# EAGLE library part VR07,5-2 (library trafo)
TRANSFORMER 1 primary winding, 2 secondary windings, mounting holes BLOCK
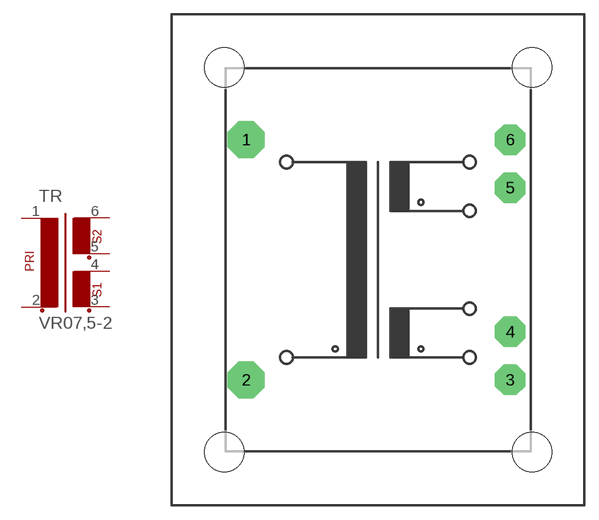
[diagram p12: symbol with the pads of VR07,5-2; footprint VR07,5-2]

Designator prefix TR

## VR07,5-2  [VR07,5-2]
1  1  pas
2  2  pas
3  3  pas
4  4  pas
5  5  pas
6  6  pas

## Footprint VR07,5-2 (pad centres in mm)
TRANSFORMER 1 primary winding, 2 secondary windings, mounting holes
drill 1.397 pad 3.81 octagon: 1 -13.741,12.497; 2 -13.741,-12.497
drill 1.397 pad 3.175 octagon: 3 13.741,-12.497; 4 13.741,-7.493; 5 13.741,7.493; 6 13.741,12.497
hole 4.115 at -16.002,-19.99
hole 4.115 at 16.002,-19.99
hole 4.115 at 16.002,19.99
hole 4.115 at -16.002,19.99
